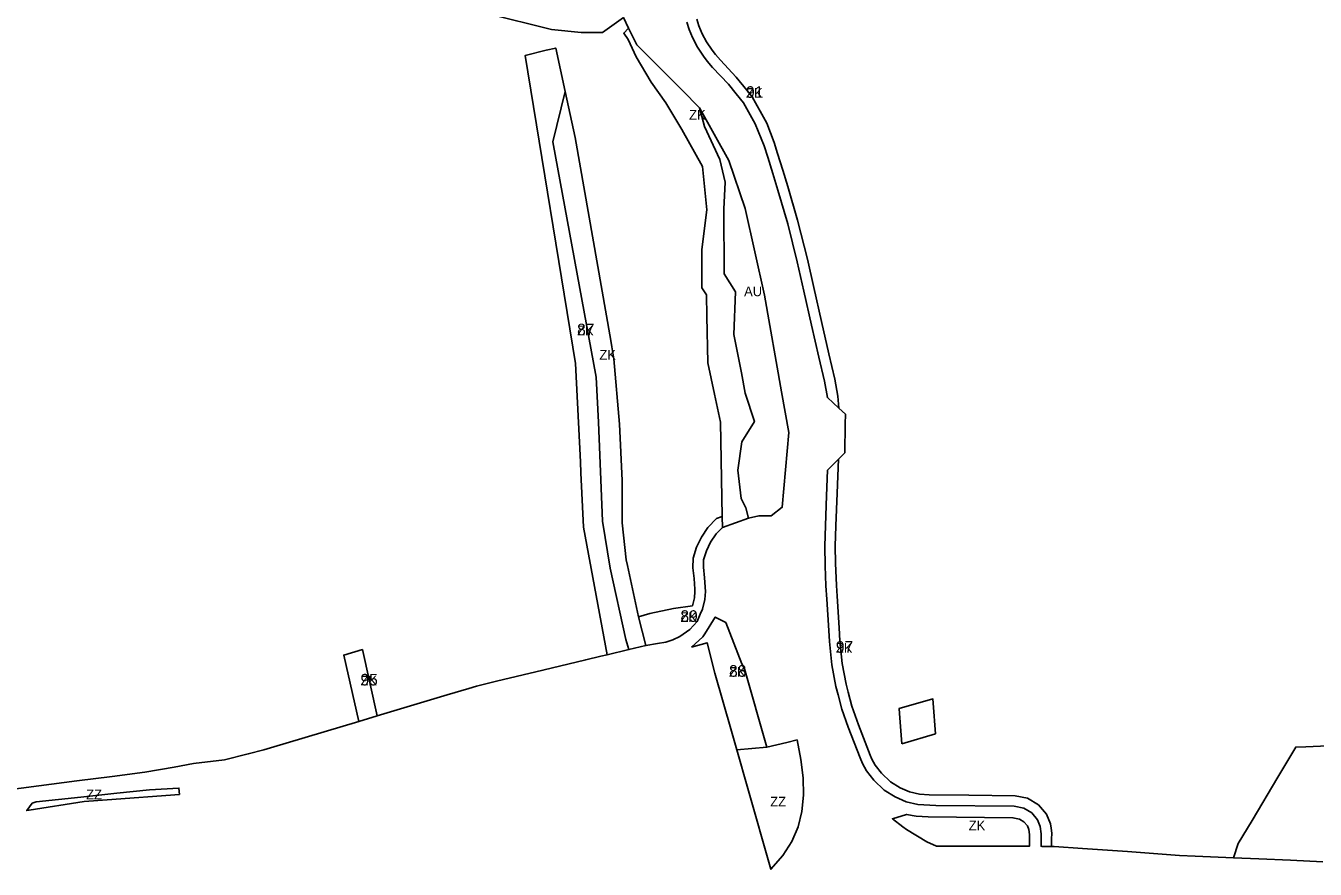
# Model space of a CAD drawing. Extents: x -535894 to -532834, y -1165802 to -1163647.
# Drawn here: x -534347 to -533682, y -1164810 to -1164374 of the extents above; entities that cross this region are included whole.
import ezdxf

# ---------------------------------------------------------------- set-up
doc = ezdxf.new("R2010")
doc.units = 0
for name, color, linetype in [('Vrstva 10', 7, 'Continuous'), ('Vrstva 16', 7, 'Continuous'), ('Vrstva 17', 7, 'Continuous'), ('Vrstva 19', 7, 'Continuous'), ('Vrstva 22', 7, 'Continuous'), ('Vrstva 34', 7, 'Continuous'), ('Vrstva 61', 7, 'Continuous')]:
    doc.layers.add(name, color=color, linetype=linetype)

msp = doc.modelspace()

# ---------------------------------------------------------------- linework, layer by layer
at = {"layer": 'Vrstva 10'}
for points in [[(-533949.63, -1164742.72), (-533947.667, -1164752.915), (-533946.509, -1164762.433), (-533946.273, -1164771.351), (-533947.08, -1164779.742), (-533949.047, -1164787.683), (-533952.293, -1164795.247), (-533956.938, -1164802.511), (-533963.1, -1164809.55), (-533974.92, -1164767.93), (-533980.66, -1164747.97), (-533965.282, -1164746.513), (-533954.82, -1164744.13)], [(-534345.63, -1164779.09), (-534346.921, -1164779.295), (-534344.157, -1164775.523), (-534342.086, -1164774.76), (-534319.12, -1164772.3), (-534300.47, -1164770.31), (-534283.7, -1164768.52), (-534268.47, -1164767.68), (-534268.21, -1164770.94), (-534305.43, -1164773.71), (-534317.28, -1164774.6)]]:
    msp.add_lwpolyline(points, close=True, dxfattribs=at)
at = {"layer": 'Vrstva 16'}
for points in [[(-533980.243, -1164603.706), (-533978.441, -1164618.244), (-533976.098, -1164623.116), (-533974.64, -1164628.33), (-533988.116, -1164633.161), (-533988.217, -1164627.461), (-533989.08, -1164578.89), (-533992.16, -1164564.37), (-533995.59, -1164548.2), (-533996.11, -1164524.23), (-533996.35, -1164513.15), (-533998.71, -1164509.47), (-533998.67, -1164489.69), (-533996.14, -1164469.25), (-533998.31, -1164446.91), (-534009.02, -1164427.79), (-534017.28, -1164414.13), (-534024.85, -1164403.44), (-534032.655, -1164390.41), (-534036.75, -1164381.38), (-534039.039, -1164378.104), (-534036.523, -1164375.518), (-534032.22, -1164384.15), (-534008.94, -1164407.6), (-533999.91, -1164416.7), (-533997.305, -1164426.361), (-533989.435, -1164443.303), (-533986.731, -1164455.018), (-533987.402, -1164468.935), (-533987.212, -1164502.297), (-533981.445, -1164511.669), (-533982.286, -1164533.657), (-533978.321, -1164553.482), (-533976.293, -1164563.841), (-533971.592, -1164578.474), (-533978.08, -1164589.047)], [(-534027.567, -1164694.184), (-534036.347, -1164696.241), (-534037.87, -1164691), (-534046.04, -1164654.24), (-534050.05, -1164630.03), (-534052.06, -1164578.82), (-534053.31, -1164555.72), (-534075.643, -1164434.195), (-534069.206, -1164408.204), (-534064.01, -1164431.89), (-534045.697, -1164536.686), (-534045.118, -1164539.999), (-534044.05, -1164546.11), (-534041.27, -1164579.97), (-534039.76, -1164609.03), (-534039.76, -1164630.76), (-534037.74, -1164649.96), (-534037.13, -1164652.786), (-534031.42, -1164679.27)], [(-533829.99, -1164789.083), (-533829.653, -1164791.654), (-533829.713, -1164797.731), (-533845.77, -1164797.71), (-533863.74, -1164797.68), (-533872.62, -1164797.667), (-533877.62, -1164797.66), (-533882.672, -1164795.392), (-533893.072, -1164788.969), (-533894.971, -1164787.721), (-533900.403, -1164783.498), (-533893.097, -1164781.251), (-533888.18, -1164782.112), (-533881.993, -1164782.599), (-533838.263, -1164782.986), (-533834.874, -1164783.646), (-533832.553, -1164785.078), (-533830.802, -1164787.167)]]:
    msp.add_lwpolyline(points, close=True, dxfattribs=at)
at = {"layer": 'Vrstva 17'}
msp.add_lwpolyline([(-534001.319, -1164370.935), (-534000.209, -1164374.396), (-533998.504, -1164378.422), (-533996.347, -1164382.535), (-533993.474, -1164386.916), (-533991.741, -1164389.202), (-533989.151, -1164392.146), (-533980.953, -1164400.872), (-533975.542, -1164407.6), (-533972.808, -1164410.999), (-533966.033, -1164423.017), (-533965.126, -1164424.627), (-533961.413, -1164434.502), (-533959.646, -1164440.241), (-533957.009, -1164448.806), (-533954.388, -1164457.318), (-533949.353, -1164474.635), (-533944.307, -1164494.798), (-533940.976, -1164509.392), (-533936.964, -1164526.968), (-533933.166, -1164543.613), (-533930.187, -1164556.665), (-533928.565, -1164565.452), (-533928.047, -1164571.612), (-533933.924, -1164566.171), (-533935.477, -1164557.756), (-533938.311, -1164545.337), (-533942.1, -1164528.737), (-533946.1, -1164511.207), (-533949.559, -1164496.052), (-533954.432, -1164476.512), (-533954.435, -1164476.499), (-533959.457, -1164459.206), (-533962.096, -1164450.634), (-533964.719, -1164442.117), (-533966.526, -1164436.248), (-533971.181, -1164424.882), (-533977.295, -1164414.037), (-533980.978, -1164409.457), (-533985.031, -1164404.418), (-533993.148, -1164395.779), (-533995.925, -1164392.62), (-533997.888, -1164390.031), (-534001.007, -1164385.276), (-534003.546, -1164380.408), (-534005.28, -1164376.266), (-534006.517, -1164372.409)], dxfattribs=at)
for points in [[(-534047.573, -1164698.892), (-534059.702, -1164633.021), (-534061.096, -1164605.058), (-534061.383, -1164599.296), (-534063.908, -1164548.655), (-534089.79, -1164389.609), (-534079.019, -1164386.986), (-534074.121, -1164385.794), (-534069.206, -1164408.204), (-534075.643, -1164434.195), (-534053.31, -1164555.72), (-534052.06, -1164578.82), (-534050.05, -1164630.03), (-534046.04, -1164654.24), (-534037.87, -1164691), (-534036.347, -1164696.241)], [(-533928.916, -1164615.571), (-533929.623, -1164632.405), (-533929.869, -1164642.887), (-533929.73, -1164651.557), (-533929.309, -1164663.085), (-533928.959, -1164668.689), (-533927.942, -1164684.931), (-533927.524, -1164691.616), (-533926.278, -1164703.392), (-533924.356, -1164714.063), (-533923.276, -1164718.117), (-533921.345, -1164725.365), (-533917.93, -1164735.018), (-533911.854, -1164750.682), (-533910.983, -1164752.718), (-533909.296, -1164755.821), (-533906.059, -1164760.027), (-533901.349, -1164764.446), (-533896.496, -1164767.476), (-533891.589, -1164769.598), (-533886.416, -1164770.815), (-533881.495, -1164771.203), (-533861.014, -1164771.384), (-533837.114, -1164771.596), (-533830.656, -1164772.853), (-533824.999, -1164776.343), (-533820.971, -1164781.149), (-533818.889, -1164786.062), (-533818.577, -1164788.435), (-533818.245, -1164790.965), (-533818.276, -1164794.075), (-533818.312, -1164797.756), (-533820.59, -1164797.75), (-533823.21, -1164797.74), (-533823.713, -1164797.739), (-533823.66, -1164792.468), (-533823.649, -1164791.291), (-533824.147, -1164787.493), (-533824.518, -1164786.617), (-533825.628, -1164784), (-533828.577, -1164780.481), (-533832.654, -1164777.966), (-533837.659, -1164776.992), (-533878.083, -1164776.633), (-533887.252, -1164776.166), (-533893.292, -1164774.744), (-533899.011, -1164772.271), (-533904.657, -1164768.747), (-533910.072, -1164763.667), (-533913.837, -1164758.775), (-533915.848, -1164755.075), (-533917.13, -1164752.07), (-533923.227, -1164736.291), (-533926.509, -1164726.959), (-533928.481, -1164719.555), (-533929.632, -1164715.238), (-533931.627, -1164704.155), (-533932.906, -1164692.069), (-533933.268, -1164686.286), (-533934.278, -1164670.147), (-533934.702, -1164663.366), (-533935.108, -1164652.972), (-533935.27, -1164642.867), (-533935.021, -1164632.229), (-533934.374, -1164616.826), (-533933.845, -1164603.579), (-533928.175, -1164597.927)], [(-534003.577, -1164673.621), (-534002.465, -1164669.521), (-534002.308, -1164666.315), (-534002.382, -1164665.123), (-534002.722, -1164659.614), (-534003.325, -1164653.975), (-534003.247, -1164649.051), (-534001.408, -1164643.336), (-533998.933, -1164638.18), (-533995.569, -1164633.138), (-533991.136, -1164628.507), (-533988.217, -1164627.461), (-533988.116, -1164633.161), (-533991.34, -1164636.53), (-533994.23, -1164640.86), (-533996.38, -1164645.34), (-533997.86, -1164649.94), (-533997.92, -1164653.73), (-533997.34, -1164659.16), (-533996.9, -1164666.28), (-533997.1, -1164670.37), (-533998.47, -1164675.42), (-533999.598, -1164677.998), (-534001.2, -1164681.66), (-534004.94, -1164685.91), (-534010.017, -1164689.514), (-534013.67, -1164691.24), (-534017.22, -1164692.32), (-534021.634, -1164693.103), (-534027.567, -1164694.184), (-534031.42, -1164679.27), (-534025.511, -1164677.617), (-534013.382, -1164675.046)], [(-534004.077, -1164694.939), (-533998.16, -1164689.6), (-533997.187, -1164688.034), (-533991.85, -1164679.44), (-533986.32, -1164682.27), (-533978.18, -1164703.55), (-533976.638, -1164706.229), (-533965.282, -1164746.513), (-533980.66, -1164747.97), (-533983.41, -1164738.37), (-533992.01, -1164708.4), (-533996.002, -1164692.697)], [(-534173.855, -1164696.182), (-534166.143, -1164730.401), (-534175.745, -1164733.28), (-534183.458, -1164699.055)]]:
    msp.add_lwpolyline(points, close=True, dxfattribs=at)
at = {"layer": 'Vrstva 19'}
msp.add_lwpolyline([(-534039.205, -1164370.137), (-534049.915, -1164377.707), (-534061.023, -1164377.707), (-534076.23, -1164376.18), (-534079.11, -1164375.48), (-534106.79, -1164368.71)], dxfattribs=at)
at = {"layer": 'Vrstva 22'}
for points in [[(-534106.79, -1164368.71), (-534079.11, -1164375.48), (-534076.23, -1164376.18), (-534061.023, -1164377.707), (-534049.915, -1164377.707), (-534039.205, -1164370.137), (-534036.523, -1164375.518), (-534039.039, -1164378.104), (-534036.75, -1164381.38), (-534032.655, -1164390.41), (-534024.85, -1164403.44), (-534017.28, -1164414.13), (-534009.02, -1164427.79), (-533998.31, -1164446.91), (-533996.14, -1164469.25), (-533998.67, -1164489.69), (-533998.71, -1164509.47), (-533996.35, -1164513.15), (-533996.11, -1164524.23), (-533995.59, -1164548.2), (-533992.16, -1164564.37), (-533989.08, -1164578.89), (-533988.217, -1164627.461), (-533991.136, -1164628.507), (-533995.569, -1164633.138), (-533998.933, -1164638.18), (-534001.408, -1164643.336), (-534003.247, -1164649.051), (-534003.325, -1164653.975), (-534002.722, -1164659.614), (-534002.382, -1164665.123), (-534002.308, -1164666.315), (-534002.465, -1164669.521), (-534003.577, -1164673.621), (-534013.382, -1164675.046), (-534025.511, -1164677.617), (-534031.42, -1164679.27), (-534037.13, -1164652.786), (-534037.74, -1164649.96), (-534039.76, -1164630.76), (-534039.76, -1164609.03), (-534041.27, -1164579.97), (-534044.05, -1164546.11), (-534045.118, -1164539.999), (-534045.697, -1164536.686), (-534064.01, -1164431.89), (-534069.206, -1164408.204), (-534074.121, -1164385.794), (-534079.019, -1164386.986), (-534089.79, -1164389.609), (-534063.908, -1164548.655), (-534061.383, -1164599.296), (-534061.096, -1164605.058), (-534059.702, -1164633.021), (-534047.573, -1164698.892), (-534050.857, -1164699.668), (-534058.603, -1164701.497), (-534080.73, -1164706.916), (-534104.663, -1164712.55), (-534114.899, -1164715.096), (-534118.867, -1164716.27), (-534130.015, -1164719.567), (-534166.143, -1164730.401), (-534173.855, -1164696.182), (-534183.458, -1164699.055), (-534175.745, -1164733.28), (-534221.258, -1164746.894), (-534224.583, -1164747.891), (-534232.713, -1164750.025), (-534245.02, -1164753.04), (-534260.885, -1164754.965), (-534270.957, -1164756.824), (-534286.069, -1164759.45), (-534302.826, -1164761.623), (-534321.12, -1164763.995), (-534369.617, -1164770.285)], [(-533656.85, -1164745.055), (-533687.212, -1164746.337), (-533692.373, -1164746.555), (-533701.613, -1164762.037), (-533714.936, -1164784.359), (-533722.061, -1164796.295), (-533724.542, -1164803.644), (-533744.22, -1164802.78), (-533752.3, -1164802.43), (-533779.21, -1164800.48), (-533802.41, -1164798.81), (-533817.02, -1164797.76), (-533818.312, -1164797.756), (-533818.276, -1164794.075), (-533818.245, -1164790.965), (-533818.577, -1164788.435), (-533818.889, -1164786.062), (-533820.971, -1164781.149), (-533824.999, -1164776.343), (-533830.656, -1164772.853), (-533837.114, -1164771.596), (-533861.014, -1164771.384), (-533881.495, -1164771.203), (-533886.416, -1164770.815), (-533891.589, -1164769.598), (-533896.496, -1164767.476), (-533901.349, -1164764.446), (-533906.059, -1164760.027), (-533909.296, -1164755.821), (-533910.983, -1164752.718), (-533911.854, -1164750.682), (-533917.93, -1164735.018), (-533921.345, -1164725.365), (-533923.276, -1164718.117), (-533924.356, -1164714.063), (-533926.278, -1164703.392), (-533927.524, -1164691.616), (-533927.942, -1164684.931), (-533928.959, -1164668.689), (-533929.309, -1164663.085), (-533929.73, -1164651.557), (-533929.869, -1164642.887), (-533929.623, -1164632.405), (-533928.916, -1164615.571), (-533928.175, -1164597.927), (-533925.006, -1164594.768), (-533924.728, -1164579.85), (-533924.633, -1164574.772), (-533928.047, -1164571.612), (-533928.565, -1164565.452), (-533930.187, -1164556.665), (-533933.166, -1164543.613), (-533936.964, -1164526.968), (-533940.976, -1164509.392), (-533944.307, -1164494.798), (-533949.353, -1164474.635), (-533954.388, -1164457.318), (-533957.009, -1164448.806), (-533959.646, -1164440.241), (-533961.413, -1164434.502), (-533965.126, -1164424.627), (-533966.033, -1164423.017), (-533972.808, -1164410.999), (-533975.542, -1164407.6), (-533980.953, -1164400.872), (-533989.151, -1164392.146), (-533991.741, -1164389.202), (-533993.474, -1164386.916), (-533996.347, -1164382.535), (-533998.504, -1164378.422), (-534000.209, -1164374.396), (-534001.319, -1164370.935)]]:
    msp.add_lwpolyline(points, dxfattribs=at)
for points in [[(-533976.293, -1164563.841), (-533978.321, -1164553.482), (-533982.286, -1164533.657), (-533981.445, -1164511.669), (-533987.212, -1164502.297), (-533987.402, -1164468.935), (-533986.731, -1164455.018), (-533989.435, -1164443.303), (-533997.305, -1164426.361), (-533999.91, -1164416.7), (-533984.74, -1164443.86), (-533976.42, -1164468.54), (-533966.49, -1164513.4), (-533957.65, -1164563.22), (-533953.92, -1164584.19), (-533957.211, -1164622.742), (-533963.011, -1164627.201), (-533969.29, -1164627.24), (-533974.64, -1164628.33), (-533976.098, -1164623.116), (-533978.441, -1164618.244), (-533980.243, -1164603.706), (-533978.08, -1164589.047), (-533971.592, -1164578.474)], [(-533895.56, -1164744.9), (-533878.24, -1164739.68), (-533879.34, -1164723.78), (-533879.49, -1164721.65), (-533896.98, -1164726.69), (-533896.78, -1164729.16)]]:
    msp.add_lwpolyline(points, close=True, dxfattribs=at)
at = {"layer": 'Vrstva 34'}
msp.add_lwpolyline([(-533678.4, -1164805.66), (-533695.1, -1164804.93), (-533711.44, -1164804.22), (-533724.542, -1164803.644), (-533722.061, -1164796.295), (-533714.936, -1164784.359), (-533701.613, -1164762.037), (-533692.373, -1164746.555), (-533687.212, -1164746.337), (-533656.85, -1164745.055)], dxfattribs=at)

# ---------------------------------------------------------------- texts
at = {"layer": 'Vrstva 10'}
msp.add_text('ZZ', height=5, dxfattribs=at).set_placement((-534316.3233, -1164773.4875))
msp.add_text('ZZ', height=5, rotation=360, dxfattribs=at).set_placement((-533963.4665, -1164777.1795))
at = {"layer": 'Vrstva 16'}
for rotation, p in [(0, (-534005.3155, -1164422.828)), (360, (-534051.605, -1164546.6449)), (360, (-533861.0817, -1164789.491))]:
    msp.add_text('ZK', height=5, rotation=rotation, dxfattribs=at).set_placement(p)
at = {"layer": 'Vrstva 17'}
for rotation, p in [(0, (-533975.9286, -1164411.5025)), (359.9999999, (-534063.0685, -1164534.0555)), (0, (-534009.768, -1164681.929)), (360, (-533929.5802, -1164697.8415)), (360, (-534174.8005, -1164714.7308)), (0, (-533984.6795, -1164710.2523))]:
    msp.add_text('ZK', height=5, rotation=rotation, dxfattribs=at).set_placement(p)
at = {"layer": 'Vrstva 22'}
msp.add_text('AU', height=5, rotation=359.9999999, dxfattribs=at).set_placement((-533976.915, -1164513.8677))
at = {"layer": 'Vrstva 61'}
for s, rotation, p in [('91', 360, (-533975.9286, -1164411.5025)), ('87', 0, (-534063.0685, -1164534.0555)), ('89', 0, (-534009.768, -1164681.929)), ('97', 360, (-533929.5802, -1164697.8415)), ('88', 0.0000001, (-533984.6795, -1164710.2523)), ('95', 360, (-534174.8005, -1164714.7308))]:
    msp.add_text(s, height=6, rotation=rotation, dxfattribs=at).set_placement(p)

doc.saveas('drawing.dxf')
